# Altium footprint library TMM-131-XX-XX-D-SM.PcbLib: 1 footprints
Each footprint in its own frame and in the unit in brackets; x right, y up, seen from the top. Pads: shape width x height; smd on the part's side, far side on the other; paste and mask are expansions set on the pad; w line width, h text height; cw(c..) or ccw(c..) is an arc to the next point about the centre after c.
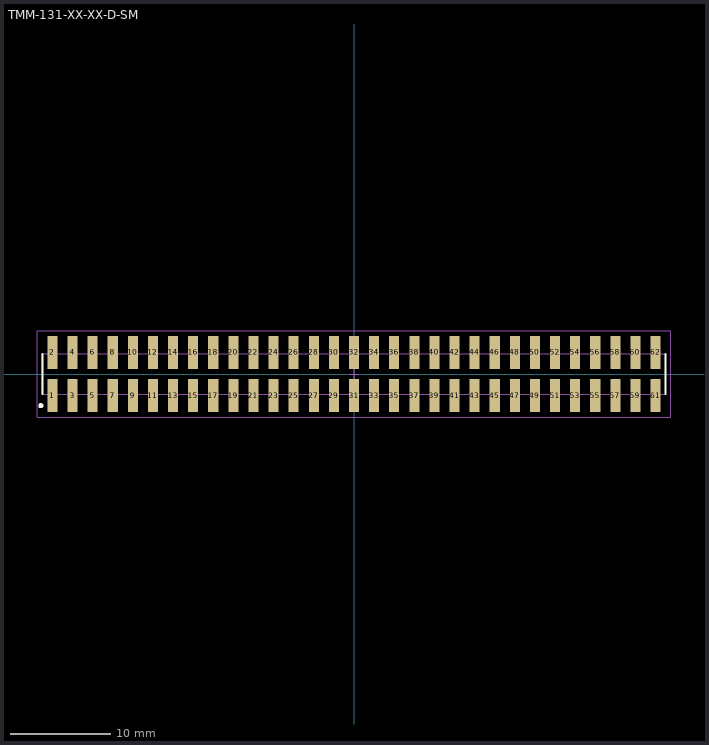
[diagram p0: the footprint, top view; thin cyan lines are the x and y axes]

## TMM-131-XX-XX-D-SM [mm] "2.00mm pitch, 62 pin, terminal strip; double row, SMT"
height 2.77
pads (62):
  rect 1x3.3 smd mask+0: 1(-30,-2.15) 2(-30,2.15) 3(-28,-2.15) 4(-28,2.15) 5(-26,-2.15) 6(-26,2.15) 7(-24,-2.15) 8(-24,2.15) 9(-22,-2.15) 10(-22,2.15) 11(-20,-2.15) 12(-20,2.15) 13(-18,-2.15) 14(-18,2.15) 15(-16,-2.15) 16(-16,2.15) 17(-14,-2.15) 18(-14,2.15) 19(-12,-2.15) 20(-12,2.15) 21(-10,-2.15) 22(-10,2.15) 23(-8,-2.15) 24(-8,2.15) 25(-6,-2.15) 26(-6,2.15) 27(-4,-2.15) 28(-4,2.15) 29(-2,-2.15) 30(-2,2.15) 31(0,-2.15) 32(0,2.15) 33(2,-2.15) 34(2,2.15) 35(4,-2.15) 36(4,2.15) 37(6,-2.15) 38(6,2.15) 39(8,-2.15) 40(8,2.15) 41(10,-2.15) 42(10,2.15) 43(12,-2.15) 44(12,2.15) 45(14,-2.15) 46(14,2.15) 47(16,-2.15) 48(16,2.15) 49(18,-2.15) 50(18,2.15) 51(20,-2.15) 52(20,2.15) 53(22,-2.15) 54(22,2.15) 55(24,-2.15) 56(24,2.15) 57(26,-2.15) 58(26,2.15) 59(28,-2.15) 60(28,2.15) 61(30,-2.15) 62(30,2.15)
Top Overlay:
  circle w0.25: c-31.15,-3.15 r0.125
  lines w0.2: -31,-2 -31,2 ; 31,-2 31,2
Mechanical 12:
  lines w0.001: -31,-2 31,-2 31,2 -31,2 -31,-2
Mechanical 13:
  lines w0.1: -31,-2 31,-2 31,2 -31,2 -31,-2
  text ".Designator" at 0,-0.127 h1.52
Mechanical 15:
  lines w0.05: -0.5,0 0.5,0 ; 0,-0.5 0,0.5 ; -31.5,-4.3 31.5,-4.3 31.5,4.3 -31.5,4.3 -31.5,-4.3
